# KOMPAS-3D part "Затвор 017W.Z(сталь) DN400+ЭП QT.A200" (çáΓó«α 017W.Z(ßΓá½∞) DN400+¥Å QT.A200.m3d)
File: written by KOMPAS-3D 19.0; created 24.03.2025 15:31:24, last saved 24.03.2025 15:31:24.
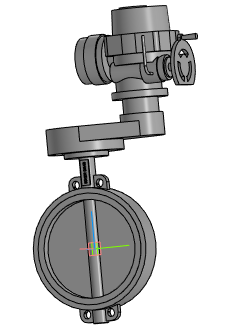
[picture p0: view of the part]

Document properties: Полное имя файла: Затвор 017W.Z(сталь) DN400+ЭП QT.A200.a3d

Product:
- Part/product: Затвор 017W.Z(сталь) DN400+ЭП QT.A200
    Масса: 317.862

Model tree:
1. Операция без истории:1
